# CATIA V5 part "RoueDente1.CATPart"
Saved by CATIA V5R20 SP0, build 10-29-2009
Part number: pignon.1
Source: Unknown
Publications: "Esquisse.8", "Plan.3"
Material "Rouge DS": density 7860 kg/m3, Young's modulus 2e+11 Pa, Poisson ratio 0.266
Bounding box of the stored display mesh (mm): x 0 to 5, y -22.496 to 22.496, z -22.466 to 22.496
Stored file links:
  E:\EDELI\gcausse\Edeli_2012_233_gcausse\RoueDente1.CATPart
  C:\usr\gt1\projet\site_web\doc\catia\gears\spur_gear_files\parts\gear_n.CATPart
  C:\Users\thinkmotion1\Desktop\Nouveau dossier\Cremai_Automobile\Cremaillere_automobile.CATProduct
  C:\Program Files\Dassault Systemes\B20\win_b64\startup\materials\French\Catalog.CATMaterial
  C:\Program Files\Dassault Systemes\B20\win_b64\startup\materials\red_env_512x512.jpg
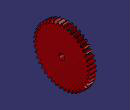
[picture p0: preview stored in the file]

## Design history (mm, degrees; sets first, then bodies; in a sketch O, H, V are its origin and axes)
Parameters
  a = 20 deg
  m = 1 mm
  Z = 43
  rp = 21.5 mm {= m * Z / 2}
  ra = 22.5 mm {= rp + m}
  rb = 20.2034 mm {= rp * cos( a )}
  rf = 20.25 mm {= rp - 1.25 * m}
  rc = 0.38 mm {= m * 0.38}
  c = 0.115855 {= sqrt( 1 / ( cos( a ) * cos( a ) ) - 1 ) / PI}
  phi = 2.947 deg
  `diametre perçages extérieurs` = 35 mm
Set1
  DatumCurve1: linked copy from another document
Set2
  Line1 "Axe X": stored without definition
  Plane1: type Angle, RefPlane zx-plane, Direction Line1, Angle 4.186 {= 180deg / Z}
  Point1 "origine": (0, 0, 0)
  Point2: (0, 0, 20.2034)
  Point3: (0, 0.2068, 21.1759)
  Point4: (0, 1.6055, 23.8063)
  Point5: (0, 5.1527, 27.2799)
  Point6: (0, 11.3691, 30.3889)
  Curve1: Elements (Point2; Point3; Point4; Point5; Point6)
  Extrapol1: ToExtrapol Point2, Support Curve1, Length 2 {= m * 2}
  Rotate1: Axis Line1, Angle 2.947 {= phi}, ToTransfor Extrapol1
  Circle1: type CtrRad, Start 0, End 180, Center Point1, Support yz-plane, Radius 20.25 {= rf}, FirstDirection (0, 1, 0)
  Circle2: type CtrRad, Start 0, End 180, Center Point1, Support yz-plane, Radius 22.5 {= ra}, FirstDirection (0, 1, 0)
  Corner1: Element1 Rotate1, Element2 Circle1, Radius 0.38 {= rc}
  Symmetry1: Reference Plane1, ToTransfor Corner1
  Split1: ToCut Rotate1, Cutting (Corner1; Circle2)
  Symmetry2: Reference zx-plane, ToTransfor Split1
  Circle3: type 2PointsRad, Start 0, End 180, FirstPoint vertex of Symmetry1, SecondPoint vertex of Corner1, Support yz-plane, Radius 20.25 {= rf}
  Circle4: type 2PointsRad, Start 0, End 180, FirstPoint vertex of Split1, SecondPoint vertex of Symmetry2, Support yz-plane, Radius 22.5 {= ra}
  Join1: Elements (Symmetry1; Circle3; Corner1; Split1; Circle4; Symmetry2)
  CircPattern1: of Join1, instances 43 {= Z}, angular step 8.3721 {= 360.0*1 deg/CircPattern1.AngularNumber}, axis from Line1
  Join2: Elements (Join1; CircPattern1)
  Plane2: type Offset, RefPlane yz-plane, Offset 33
  Sketch1 on start face of Pad1, origin (0, 0, 0), H (0, -1, 0), V (0, 0, 1)
    circle A1 centre (0, 0) radius 2.5
    radius A1 = 2.5
Body1 (main body)
  Pad1: profile Join2, length 5
  Sketch2 on Plane2, origin (33, 0, 0), H (0, 1, 0), V (0, 0, 1)
    circle A1 centre (0, 0) radius 31.6677
    radius A1 = 31.6677
  Sketch3 on start face of Pad1, origin (0, 0, 0), H (0, -1, 0), V (0, 0, 1)
    circle A1 centre (0, 0) radius 10
    radius A1 = 10
  Sketch4 on end face of Pad1, origin (5, 0, 0), H (0, 1, 0), V (0, 0, 1)
    circle A1 centre (0, 0) radius 10
    radius A1 = 10
  Pocket1: profile Sketch1, direction (1, 0, 0), length 5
